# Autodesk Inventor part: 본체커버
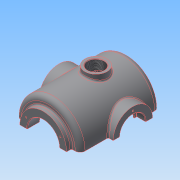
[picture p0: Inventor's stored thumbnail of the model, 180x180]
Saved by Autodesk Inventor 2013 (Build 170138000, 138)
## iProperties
Created: 2016-02
Part Number: 본체커버
Material: 알루미늄 6061
Document SubType Name: Modeling
Designer: mduedu
Density: 2.71 g/cm^3
Mass: 1187.09 g
Surface Area: 904.883 cm^2
Volume: 438.041 cm^3
Author: mduedu
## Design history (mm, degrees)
sketch "스케치2"
  geometry: L1 (0, 90)-(0, -90); L2 (65, -65.993)-(65, 90); L3 (65, 90)-(0, 90); A1 r 100 centre (0, 10) between (0, -90) and (65, -65.993); 2 further points
  constraints: 6 end point, 2 point on circle, 1 centre point, 1 coincident, 1 horizontal, 1 midpoint, 1 parallel, 1 point on line, 1 vertical
  dimensions: "d3" = 180 distance of L1.start L1.end; "d5" = 130 diameter of L2 L1; "d6" = 100 radius of A1
revolve "회전1" sketch "스케치2" stored, may be unused: angle "d7" = 90 deg
sketch "스케치3"
  geometry: C1 r 47.5 at (0, 0); 1 further point
  constraints: 1 centre point, 1 coincident
  dimensions: "d8" = 95 diameter of C1
extrude "돌출2" join sketch "스케치3" distance "d10" = 10; taper "d11" = 0 deg
sketch "스케치5"
  geometry: L1 (47.5, 100)-(47.5, 90) reference; L2 (47.5, 90)-(65, 90) reference; L3 (65, 90)-(65, -65.993) reference; L4 (-65, -65.993)-(-65, 90) reference; L5 (-65, 90)-(-47.5, 90) reference; L6 (-47.5, 90)-(-47.5, 100) reference; L7 (-47.5, 100)-(47.5, 100) reference; L8 (55, 75)-(55, -61.239); L9 (0, 75)-(55, 75); L10 (0, 75)-(0, -80); A1 r 100 centre (0, 10) between (-65, -65.993) and (0, -90) reference; A2 r 100 centre (0, 10) between (0, -90) and (65, -65.993) reference; A3 r 90 centre (0, 10) between (0, -80) and (55, -61.239); 1 further point
  constraints: 6 end point, 2 point on circle, 1 centre point, 1 parallel, 1 perpendicular, 1 point on line, 1 vertical
  dimensions: "d13" = 10 distance between parallel lines of L3 L8; "d14" = 10 radial gap between concentric circles of A3 A1; "d15" = 15 distance between parallel lines of L9 L2
revolve "회전2" sketch "스케치5" stored, may be unused: angle "d16" = 90 deg
hole "구멍1" diameter "d19" = 65; stored, may be unused: countersink angle "d23" = 90 deg, drill point angle "d25" = 118 deg; dims "d17" = 10, "d18" = 10, "d20" = 6, "d21" = 4, "d22" = 2, "d24" = 8
node "작업 평면1"
sketch "스케치6"
  geometry: L1 (47.5, 100)-(-47.5, 100) reference; C1 r 40 at (0, -7); 1 further point
  constraints: 1 centre point, 1 vertical alignment
  dimensions: "d27" = 80 diameter of C1; "d29" = 107 distance from line of C1.centre L1
extrude "돌출3" join sketch "스케치6" stored distance "d30" = 10; taper "d31" = 0 deg
hole "구멍2" diameter "d34" = 42; stored, may be unused: countersink angle "d38" = 90 deg, drill point angle "d40" = 118 deg; dims "d32" = 10, "d33" = 10, "d35" = 6, "d36" = 52, "d37" = 18, "d39" = 8
sketch "스케치7" dims "d41" = 65
  geometry: C1 r 40 at (0, 0) reference; 3 further points
  constraints: 2 vertical alignment, 1 coincident, 2 other
hole "구멍3" sketch "스케치7" at (0, 32.5) diameter "d43" = 3.242; stored, may be unused: countersink angle "d47" = 90 deg, drill point angle "d49" = 118 deg; dims "d44" = 11, "d45" = 13, "d46" = 18, "d48" = 13
sketch "스케치8" dims "d53" = 80
  geometry: 3 further points
  constraints: 2 vertical alignment, 1 coincident, 2 other
hole "구멍4" sketch "스케치8" at (0, -40) diameter "d56" = 3.242; stored, may be unused: countersink angle "d60" = 90 deg, drill point angle "d62" = 118 deg; dims "d57" = 11, "d58" = 13, "d59" = 18, "d61" = 13
fillet "모깎기1" dims "d66" = 10
fillet "모깎기2" dims "d67" = 3
fillet "모깎기3" dims "d68" = 0.3
chamfer "모따기1" distance "d69" = 1; stored, may be unused: second distance "d70" = 2, angle "d71" = 45 deg
node "작업 평면5"
sketch "스케치10"
  geometry: L1 (-50, 66)-(50, 66); L2 (50, 66)-(50, 50); L3 (50, 50)-(-50, 50); L4 (-50, 50)-(-50, 66); 2 further points
  constraints: 8 end point, 2 horizontal, 2 vertical, 1 midpoint, 1 vertical alignment
  dimensions: "d177" = 50 distance from line of L3 point (0, 0); "d178" = 100 distance of L1.start L1.end; "d179" = 16 distance of L3.end L1.start
extrude "돌출5" join sketch "스케치10" stored distance "d84" = 10; taper "d85" = 0 deg
sketch "스케치21" dims "d180" = 220, "d182" = 130
  geometry: L1 (65, 58)-(-65, 58); L2 (-65, 58)-(-65, -32); L3 (-65, -32)-(65, -32); L4 (65, -32)-(65, 58); L5 (50, 50)-(50, 66) reference; 4 further points
  constraints: 8 end point, 3 horizontal alignment, 3 midpoint, 2 parallel, 1 horizontal, 1 perpendicular, 1 vertical alignment, 4 other
extrude "돌출13" join sketch "스케치21" distance "d183" = 10; taper "d184" = 0 deg
sketch "스케치11"
  geometry: L1 (-65, 80)-(-65, -61.239) reference; L2 (-100, -97)-(-100, -32) reference; L3 (-65, -42.793)-(-100, -63); L4 (-100, -97)-(-110, -97) reference; 1 further point
  constraints: 2 end point, 2 point on line
  dimensions: "d185" = 34 distance from line of L3.end L4; "d186" = 120 deg angle of L2 L3
feature "리브1" sketch "스케치11" dims "d88" = 1, "d89" = 16, "d90" = 0, "d91" = 0, "d92" = 1, "d93" = 1
fillet "모깎기12"
fillet "모깎기13"
fillet "모깎기16" dims "d167" = 3
fillet "모깎기18"
fillet "모깎기17" dims "d168" = 3
fillet "모깎기19" dims "d187" = 3
node "작업 평면6"
sketch "스케치19"
  geometry: L1 (75, -47)-(75, 33) reference; L2 (-75, -47)-(-75, 33) reference; L3 (75, -7)-(-75, -7); C1 r 22.5 at (0, -7); 1 further point
  constraints: 3 midpoint, 2 end point, 1 centre point
  dimensions: "d149" = 45 diameter of C1
extrude "돌출11" join sketch "스케치19" stored distance "d150" = 10; taper "d151" = 0 deg
hole "구멍6" diameter "d154" = 33.376; stored, may be unused: countersink angle "d158" = 90 deg, drill point angle "d160" = 118 deg; dims "d155" = 6, "d156" = 4, "d157" = 2, "d159" = 8, "d190" = 10, "d191" = 10
fillet "모깎기11" dims "d161" = 3
chamfer "모따기3" distance "d164" = 1; stored, may be unused: second distance "d165" = 2, angle "d166" = 45 deg
sketch "스케치22" dims "d189" = 20
  geometry: L1 (-10, -123)-(10, -123); L2 (10, -123)-(10, -103); L3 (10, -103)-(-10, -103); L4 (-10, -103)-(-10, -123); A1 r 65 centre (0, -58) between (-65, -58) and (65, -58) reference; 2 further points
  constraints: 8 end point, 2 parallel, 1 horizontal, 1 horizontal alignment, 1 midpoint, 1 perpendicular, 1 tangent, 1 vertical alignment, 2 other
  dimensions: "d193" = 30 dimension on L1
extrude "돌출14" cut sketch "스케치22" stored distance "d194" = 10; taper "d195" = 0 deg
fillet "모깎기21" dims "d196" = 3
feature "분할1"
node "솔리드2"
pattern_circular "원형 패턴1" dims angle "d51" = 360 deg
mirror "대칭1"
pattern_circular "원형 패턴2" dims angle "d64" = 360 deg
node "절단 모서리 투영1"
other parameters: "d26" = 75, "d136" = 175
